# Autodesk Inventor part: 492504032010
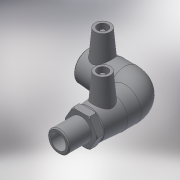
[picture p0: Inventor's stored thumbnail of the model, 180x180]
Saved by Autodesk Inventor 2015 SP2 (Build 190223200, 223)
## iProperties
Created: 2017-06
Part Number: 492504032010
Material: Generic
Description: PLASSON 90° ELBOW MALE TRANSITION 32-1"
Document SubType Name: Modeling
Designer: KIM
Mass: 121.193 g
Surface Area: 381.143 cm^2
Volume: 121.193 cm^3
Density: 1 g/cm^3
Appearance: Default
Author: KIM
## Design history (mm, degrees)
derived "492504.ipt"
feature "Solid1::492504.ipt"
tag "TaggingFeature1"
body "Solid1"
other parameters: "d2" = 44, "d4" = 27.66667, "d5" = 39.6, "d8" = 168 deg, "d10" = 16, "d11" = 5.33333, "d29" = 43, "d30" = 15, "d31" = 45.65, "d34" = 5 deg, "d41" = 4, "d42" = 14, "d43" = 0, "d48" = 61, "d49" = 32, "d50" = 27.2, "d51" = 16, "d54" = 90 deg, "d57" = 32, "d59" = 0, "d61" = 90 deg, "d86" = 3, "d87" = 0, "d93" = 0.1, "d94" = 8.5, "d95" = 33.249, "d96" = 23.2743, "d97" = 23, "d98" = 34, "d99" = 44, "d100" = 30.6, "d102" = 1.6, "d106" = 0, "d_" = 32, "L_" = 117, "D_" = 23, "A_" = 43, "d_2" = 12, "L_2" = 34, "D_1" = 44, "R_" = 33.249
